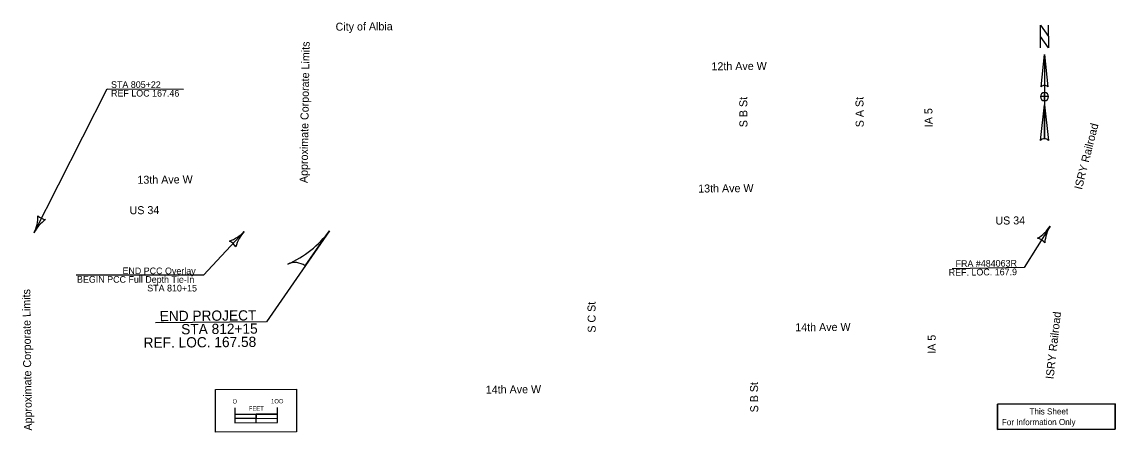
# Model space of a CAD drawing. Extents: x 22712865 to 22760106, y 6235088 to 6238602.
# Drawn here: x 22757544 to 22760106, y 6236889 to 6237851 of the extents above; entities that cross this region are included whole.
import ezdxf

# ---------------------------------------------------------------- set-up
doc = ezdxf.new("R2010")
doc.units = 0
for name, color, linetype in [('_CIVIL_CONSTRUCTION', 7, 'Continuous'), ('Default', 7, 'Continuous'), ('Draft_3', 7, 'Continuous'), ('Entrance', 7, 'Continuous')]:
    doc.layers.add(name, color=color, linetype=linetype)

msp = doc.modelspace()

# ---------------------------------------------------------------- linework, layer by layer
at = {"layer": '_CIVIL_CONSTRUCTION'}
msp.add_line((22758092.6, 6236911.7), (22758092.5, 6236931.7), dxfattribs=at)
msp.add_line((22758092.6, 6236911.7), (22758092.5, 6236931.7), dxfattribs=at)
for points in [[(22757997.3, 6236989.4), (22758187.3, 6236990), (22758187.6, 6236890), (22757997.6, 6236889.4)], [(22757997.6, 6236889.4), (22757997.3, 6236989.4), (22758187.3, 6236990), (22758187.6, 6236890)], [(22758042.6, 6236911.5), (22758092.6, 6236911.7), (22758092.5, 6236921.7), (22758042.5, 6236921.6)], [(22758092.5, 6236921.7), (22758142.5, 6236921.9), (22758142.5, 6236931.8), (22758092.5, 6236931.7)]]:
    msp.add_lwpolyline(points, close=True, dxfattribs=at)
for points in [[(22758042.5, 6236946.5), (22758042.6, 6236911.5), (22758142.6, 6236911.8), (22758142.5, 6236946.8)], [(22758042.5, 6236931.5), (22758142.5, 6236931.8)]]:
    msp.add_lwpolyline(points, dxfattribs=at)
at = {"layer": 'Draft_3'}
for p, q in [((22758207.8, 6237279.2), (22758264.8, 6237361.3)), ((22758264.1, 6237360.2), (22758264.3, 6237360.6)), ((22758207.8, 6237279.2), (22758207.8, 6237279.2))]:
    msp.add_line(p, q, dxfattribs=at)
for points in [[(22757572.2, 6237356.5), (22757743.6, 6237693.9), (22757922.2, 6237693.6)], [(22758064.8, 6237359.7), (22757969, 6237257.1), (22757670.6, 6237257.6)], [(22758264.8, 6237361.3), (22758116.6, 6237147.9), (22757857.2, 6237145.8)], [(22759953.8, 6237372.4), (22759892.7, 6237275.4), (22759723.6, 6237272.4)]]:
    msp.add_lwpolyline(points, dxfattribs=at)
for centre, radius, start, end in [((22757496.4, 6237395), 85, 333.0611, 1.1336), ((22757647.9, 6237317.9), 85, 124.9886, 153.0611), ((22757604.5, 6237420), 32.8, 225.3277, 260.7944), ((22758002.7, 6237417.7), 85, 288.895, 316.9675), ((22758127, 6237301.7), 85, 136.9675, 165.04), ((22758070.2, 6237505.2), 242, 293.5004, 323.5305), ((22759881.8, 6237417.7), 85, 299.724, 327.7965), ((22760025.7, 6237327.1), 85, 147.7965, 175.869), ((22758016.2, 6237307.6), 32.8, 29.2342, 64.7009), ((22759915.8, 6237312.1), 32.8, 40.0631, 75.5298), ((22758183.6, 6237244.4), 42.4, 55.2155, 113.5008)]:
    msp.add_arc(centre, radius, start, end, dxfattribs=at)
at = {"layer": 'Entrance'}
for p, q in [((22759940.3, 6237774.6), (22759947.9, 6237698.6)), ((22759940.3, 6237774.6), (22759940.3, 6237576.9)), ((22759932.7, 6237698.6), (22759932.7, 6237698.6)), ((22759933, 6237699.3), (22759934.4, 6237700.9)), ((22759940.3, 6237666.3), (22759940.3, 6237666.3)), ((22759930.8, 6237573.1), (22759940.3, 6237656.8))]:
    msp.add_line(p, q, dxfattribs=at)
for points in [[(22759949.8, 6237789.9), (22759930.8, 6237816.5), (22759930.8, 6237843.1), (22759949.8, 6237816.5)], [(22759830.3, 6236895.6), (22760105.9, 6236896.4), (22760105.7, 6236955.5), (22759830.1, 6236954.6)], [(22759830.1, 6236954.6), (22760105.7, 6236955.5), (22760105.9, 6236896.4), (22759830.3, 6236895.6)]]:
    msp.add_lwpolyline(points, close=True, dxfattribs=at)
for points in [[(22759930.8, 6237789.9), (22759930.8, 6237843.1), (22759949.8, 6237816.5), (22759949.8, 6237843.1)], [(22759932.7, 6237698.6), (22759940.3, 6237774.6), (22759940.3, 6237702.4)], [(22759940.3, 6237666.3), (22759940.3, 6237675.8), (22759930.8, 6237675.8)], [(22759949.8, 6237675.8), (22759940.3, 6237675.8), (22759940.3, 6237685.3)], [(22759940.3, 6237576.9), (22759940.3, 6237656.8), (22759949.8, 6237573.1)]]:
    msp.add_lwpolyline(points, dxfattribs=at)
for centre, radius, start, end in [((22759940.3, 6237692.9), 9.51, 90.0204, 143.1257), ((22759940.3, 6237692.9), 9.5, 36.8481, 90.0218), ((22759940.3, 6237675.8), 9.51, 90, 180), ((22759940.3, 6237675.8), 9.51, 180, 270), ((22759940.3, 6237675.8), 9.51, 0, 90), ((22759940.3, 6237675.8), 9.51, 270, 360), ((22759940.3, 6237563.1), 13.8, 89.9894, 133.619), ((22759940.3, 6237563.1), 13.8, 46.4021, 90.0006)]:
    msp.add_arc(centre, radius, start, end, dxfattribs=at)

# ---------------------------------------------------------------- texts
at = {"layer": '_CIVIL_CONSTRUCTION'}
for s, p in [('O', (22758037.5, 6236956.5)), ('O', (22758037.5, 6236956.5)), ('FEET', (22758075.5, 6236939.6)), ('1OO', (22758127.6, 6236956.8)), ('1OO', (22758127.6, 6236956.8))]:
    msp.add_text(s, height=10, rotation=0.1781, dxfattribs=at).set_placement(p)
at = {"layer": 'Default'}
for s, rotation, p in [('City of Albia', 0.4959, (22758279, 6237830.2)), ('Approximate Corporate Limits', 89.1519, (22758213.2, 6237473.1)), ('12th Ave W', 0.4959, (22759159.9, 6237737.4)), ('S B St', 90.4959, (22759244.2, 6237604)), ('S A St', 90.4959, (22759516.6, 6237604)), ('IA 5', 90.4959, (22759678, 6237604.1)), ('ISRY Railroad', 75.7508, (22760027.9, 6237456.6)), ('13th Ave W', 0.4959, (22757814.5, 6237471.4)), ('13th Ave W', 0.4959, (22759128.8, 6237450.9)), ('US 34', 0.4959, (22757796.1, 6237400)), ('US 34', 0.4959, (22759825.3, 6237375.8)), ('Approximate Corporate Limits', 90.7377, (22757567.4, 6236893.1)), ('S C St', 90.4959, (22758888.6, 6237122.6)), ('ISRY Railroad', 83.6196, (22759961.5, 6237012.9)), ('14th Ave W', 0.4959, (22759356.3, 6237125.6)), ('IA 5', 90.4959, (22759685.6, 6237073.1)), ('14th Ave W', 0.4959, (22758631, 6236979.7)), ('S B St', 90.4959, (22759269.5, 6236935.8))]:
    msp.add_text(s, height=18.75, rotation=rotation, dxfattribs=at).set_placement(p)
at = {"layer": 'Draft_3'}
for s, height, rotation, p in [('STA 805+22', 15.6, 359.8936, (22757752.6, 6237696.2)), ('REF LOC 167.46', 15.601, 359.8936, (22757752.6, 6237676)), ('FRA #484063R', 15.601, 0.4626, (22759732, 6237276.4)), ('BEGIN PCC Full Depth Tie-In', 15.601, 359.8936, (22757672.9, 6237239.7)), ('END PCC Overlay', 15.601, 359.8936, (22757779.4, 6237259.7)), ('REF. LOC. 167.9', 15.601, 0.4626, (22759715.9, 6237256)), ('STA 810+15', 15.6, 359.8936, (22757837.5, 6237219.2)), ('END PROJECT', 24.001, 0.4626, (22757866.8, 6237149.4)), ('STA 812+15', 24, 0.4626, (22757917.1, 6237118.7)), ('REF. LOC. 167.58', 24.001, 0.4626, (22757829, 6237087))]:
    msp.add_text(s, height=height, rotation=rotation, dxfattribs=at).set_placement(p)
at = {"layer": 'Entrance'}
for s, height, p in [('This Sheet', 14.17, (22759905.2, 6236930.7)), ('For Information Only', 14.175, (22759840.4, 6236905.6))]:
    msp.add_text(s, height=height, rotation=0.1781, dxfattribs=at).set_placement(p)

doc.saveas('drawing.dxf')
